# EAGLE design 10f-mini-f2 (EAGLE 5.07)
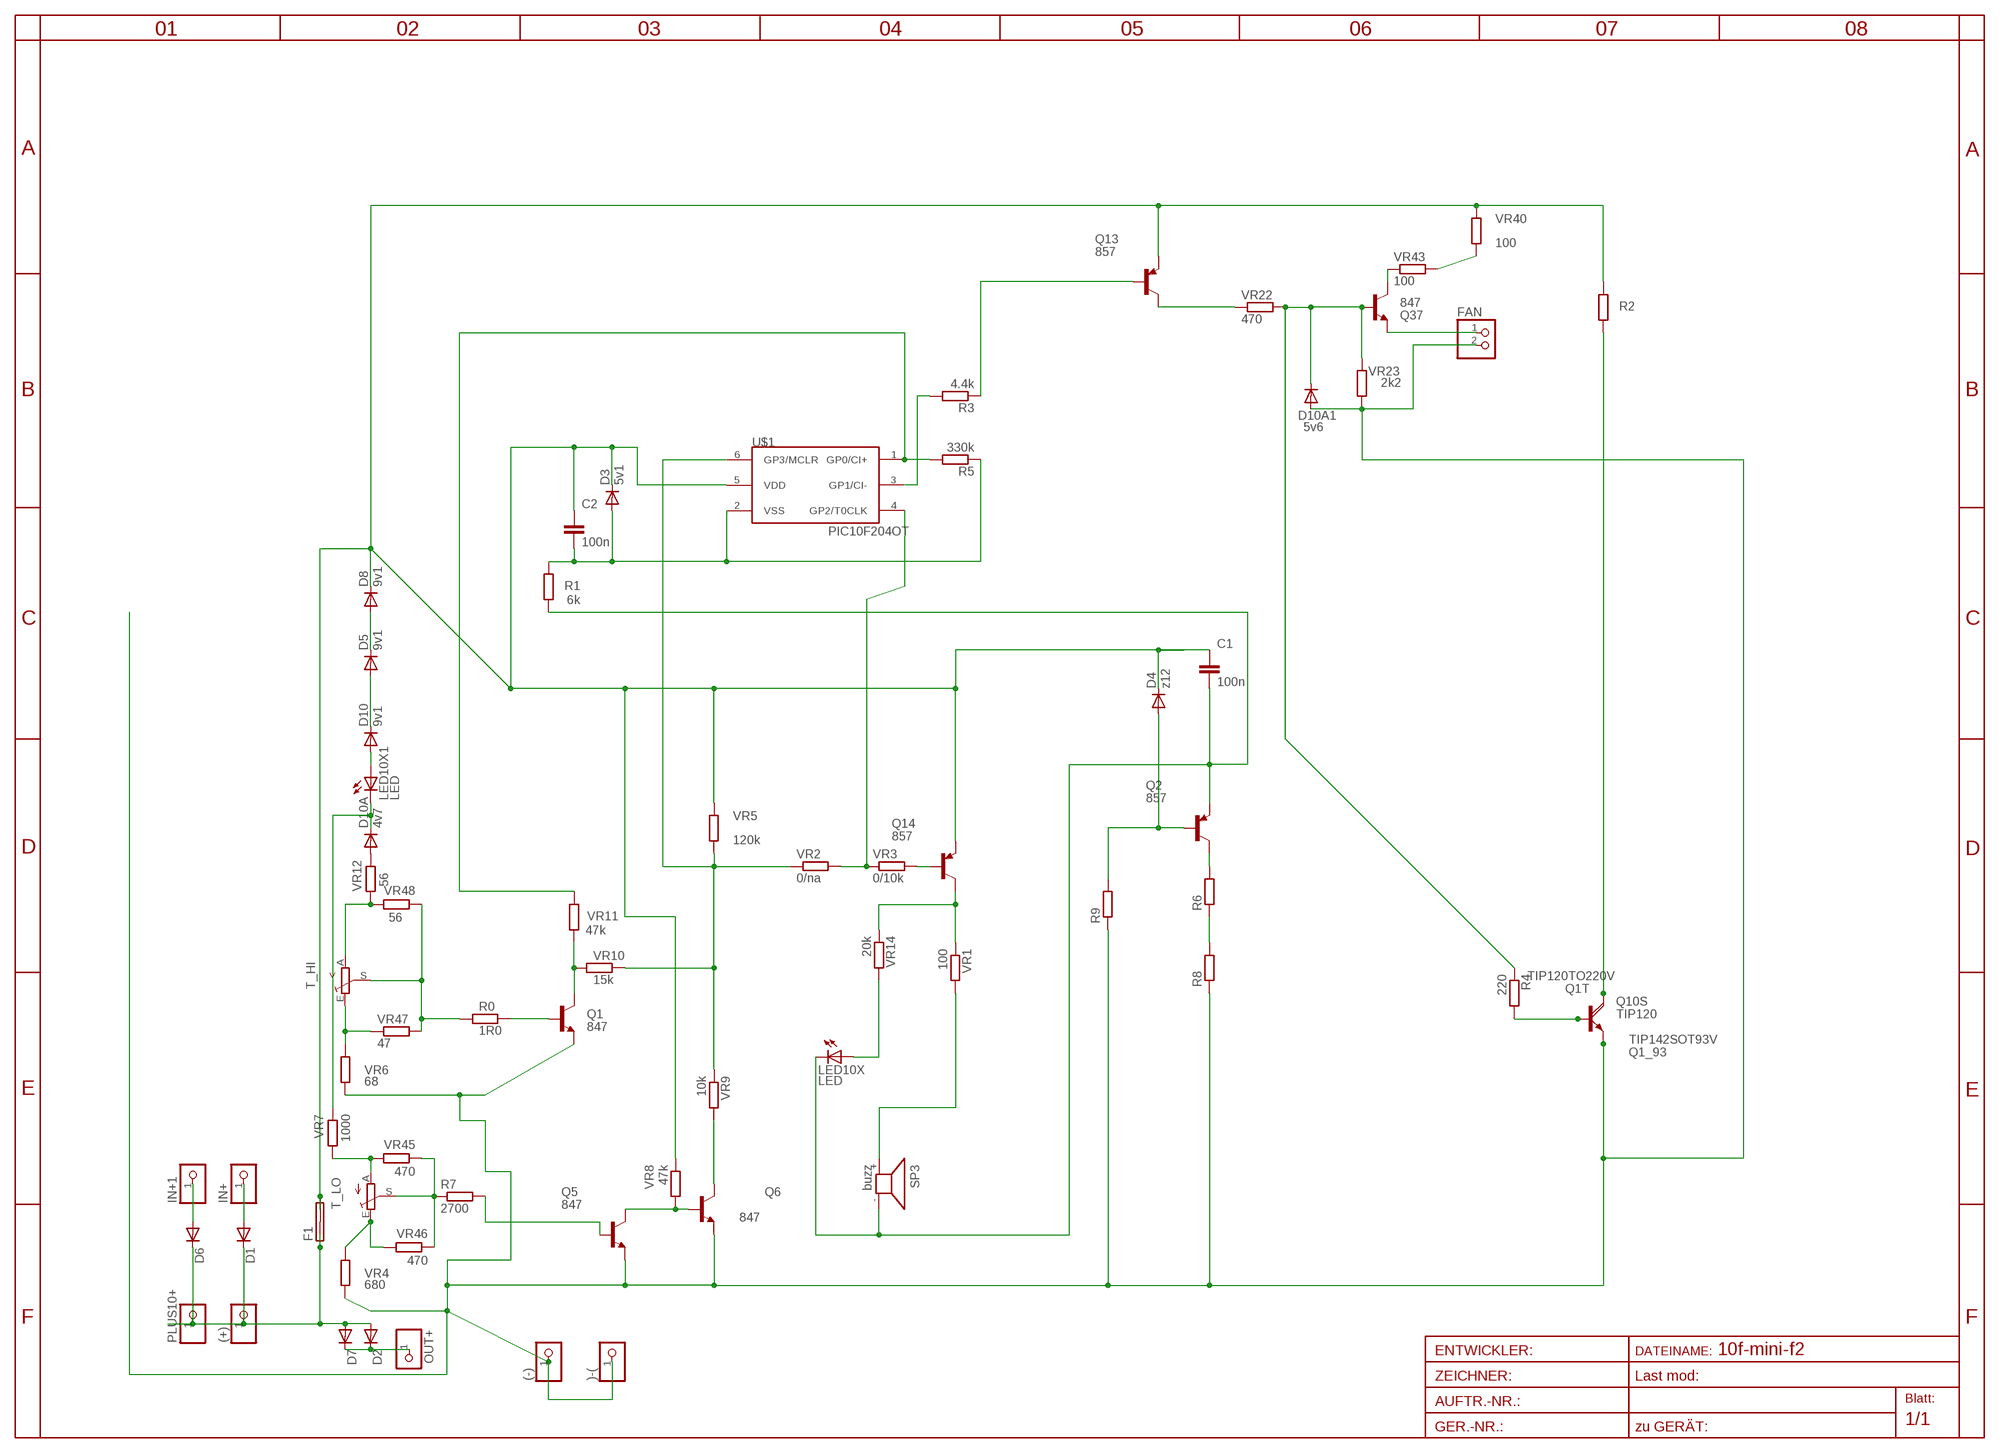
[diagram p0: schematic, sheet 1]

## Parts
(+)  PINHD-1X14.5MM  [1X4MM5]
(-)  PINHD-1X14.5MM  [1X4MM5]
)-(  PINHD-1X11X0.4  [1X01]
C1  100n  C-EUC1206  [C1206]
C2  100n  C-EUC1206  [C1206]
D1  DIODE-SMC  [SMC]
D2  DIODE-SMC  [SMC]
D3  5v1  DIODE-MINIMELF  [MINIMELF]
D4  z12  DIODE-MINIMELF  [MINIMELF]
D5  9v1  DIODE-MINIMELF  [MINIMELF]
D6  DIODE-SMC  [SMC]
D7  DIODE-SMC  [SMC]
D8  9v1  DIODE-MINIMELF  [MINIMELF]
D10  9v1  DIODE-MINIMELF  [MINIMELF]
D10A  4v7  DIODE-MINIMELF  [MINIMELF]
D10A1  5v6  DIODE-MINIMELF  [MINIMELF]
F1  SHK20L7MM5  [7MM5]
FAN  PINHD-1X2STR  [1X02]
IN+  PINHD-1X12MM3  [1X2MM3]
IN+1  PINHD-1X12MM3  [1X2MM3]
LED10X  LED  LEDCHIPLED_1206  [CHIPLED_1206]
LED10X1  LED  LEDCHIPLED_1206  [CHIPLED_1206]
OUT+  PINHD-1X12MM3  [1X2MM3]
PLUS10+  PINHD-1X11X0.4  [1X01]
Q1  847  BC847CSMD  [SOT23]
Q1_93  TIP142SOT93V  [SOT93V]
Q1T  TIP120TO220V  [TO220AV]
Q2  857  BC857CSMD  [SOT23-BEC]
Q5  847  BC847CSMD  [SOT23]
Q6  847  BC847CSMD  [SOT23]
Q10S  TIP120  TIP120DPAK  [D-PAK_TO252AA]
Q13  857  BC857CSMD  [SOT23-BEC]
Q14  857  BC857CSMD  [SOT23-BEC]
Q37  847  BC847CSMD  [SOT23]
R0  1R0  R-EU_R1206  [R1206]
R1  6k  R-EU_R1206  [R1206]
R2  R-EU_CERAM40  [CERAM40]
R3  4.4k  R-EU_R0805  [R0805]
R4  220  R-EU_R0805  [R0805]
R5  330k  R-EU_R0805  [R0805]
R6  R-EU_R1206  [R1206]
R7  2700  R-EU_R0805  [R0805]
R8  R-EU_R1206  [R1206]
R9  R-EU_R1206  [R1206]
SP3  buzz  KSS12017MM  [KSS1202]
T_HI  TRIM_EU-S64W  [S64W]
T_LO  TRIM_EU-S64W  [S64W]
U$1  PIC10F204OT  [SOT23-6]
VR1  100  R-EU_R0805  [R0805]
VR2  0/na  R-EU_R0805  [R0805]
VR3  0/10k  R-EU_R1206  [R1206]
VR4  680  R-EU_R0805  [R0805]
VR5  120k  R-EU_R0805  [R0805]
VR6  68  R-EU_R0805  [R0805]
VR7  1000  R-EU_R0805  [R0805]
VR8  47k  R-EU_R0805  [R0805]
VR9  10k  R-EU_R0805  [R0805]
VR10  15k  R-EU_R1206  [R1206]
VR11  47k  R-EU_R0805  [R0805]
VR12  56  R-EU_R0805  [R0805]
VR14  20k  R-EU_R0805  [R0805]
VR22  470  R-EU_R0805  [R0805]
VR23  2k2  R-EU_R0805  [R0805]
VR40  100  R-EU_R1206  [R1206]
VR43  100  R-EU_R1206  [R1206]
VR45  470  R-EU_R0805  [R0805]
VR46  470  R-EU_R0805  [R0805]
VR47  47  R-EU_R0805  [R0805]
VR48  56  R-EU_R0805  [R0805]

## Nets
B: R0.1 T_HI.S VR47.2 VR48.1
BUZZ+: SP3.+ VR1.2
FPLUS: C1.1 C2.1 D3.C D4.C D8.C F1.2A F1.2B Q13.E Q14.E R2.2 U$1.5(VDD) VR5.1 VR8.1 VR40.1
GP3: U$1.4(GP2/T0CLK) VR2.2 VR3.1
IN+: D1.A IN+.1
INPLUS: (+).1 D1.C D2.A D6.C D7.A F1.1A F1.1B PLUS10+.1
LEDA: LED10X.A VR14.2
N$1: D6.A IN+1.1
N$2: Q1.3(C) VR10.1 VR11.1
N$3: Q5.3(C) Q6.1(B) VR8.2
N$4: D10.A LED10X1.A
N$5: Q6.3(C) VR9.2
N$6: U$1.6(GP3/MCLR) VR2.1 VR5.2 VR9.1 VR10.2
N$7: Q1.1(B) R0.2
N$8: Q14.C VR1.1 VR14.1
N$9: D4.A Q2.B R9.2
N$10: Q14.B VR3.2
N$11: R5.2 U$1.1(GP0/CI+) VR11.2
N$12: R6.1 R8.2
N$13: Q2.C R6.2
N$14: T_HI.A VR12.2 VR48.2
N$15: D5.A D10.C
N$16: D5.C D8.A
N$17: D10A.C LED10X1.C VR7.1
N$18: D10A.A VR12.1
N$19: T_LO.A VR7.2 VR45.2
N$22: R7.1 T_LO.S VR45.1 VR46.1
N$23: Q13.B R3.1
N$24: T_LO.E VR4.1 VR46.2
N$25: Q1_93.B Q1T.B Q10S.1(B) R4.2
N$128: T_HI.E VR6.1 VR47.1
N$136: FAN.1 Q37.2(E)
N$159: Q13.C VR22.1
N$163: VR40.2 VR43.2
N$164: Q37.3(C) VR43.1
N$168: Q5.1(B) R7.2
N$179: D10A1.C Q37.1(B) R4.1 VR22.2 VR23.1
OUT+: D2.C D7.C OUT+.1
Q10C: Q1_93.C Q1T.C Q10S.4(C) R2.1
V12: C1.2 LED10X.C Q2.E R1.1 SP3.-
VDF: R3.2 U$1.3(GP1/CI-)
VSS1: C2.2 D3.A R1.2 R5.1 U$1.2(VSS)
VSS2: (-).1 )-(.1 D10A1.A FAN.2 Q1.2(E) Q1_93.E Q1T.E Q5.2(E) Q6.2(E) Q10S.3(E) R8.1 R9.1 VR4.2 VR6.2 VR23.2

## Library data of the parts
(+) (-) )-( IN+ IN+1 OUT+ PLUS10+ = pinhead:PINHD-1X1: PIN HEADER
C1 C2 = rcl:C-EU: CAPACITOR, European symbol
D1-D8 D10 D10A D10A1 = diode:DIODE-: DIODE
F1 = fuse:SHK20L: FUSE HOLDER 5 x 20 mm, SH contact, SHH1 Schukat, E1073 Buerklin
FAN = pinhead:PINHD-1X2: PIN HEADER
LED10X LED10X1 = led:LED: LED
Q1 Q5 Q6 Q37 = transistor-npn:BC847*: NPN Transistor
Q1_93 = transistor-power:TIP142: NPN DARLINGTON TRANSISTOR
Q1T Q10S = transistor-power:TIP120: NPN DARLINGTON TRANSISTOR
Q2 Q13 Q14 = transistor-pnp:BC857*: PNP Transistror
R0 R1 R3-R5 VR1-VR12 VR14 VR22 VR23 VR40 VR43 VR45-VR48 = rcl-2:R-EU_: RESISTOR, European symbol
R2 R6-R9 = rcl:R-EU_: RESISTOR, European symbol
SP3 = buzzer:KSS1201: SPEAKER
T_HI T_LO = pot:TRIM_EU-: POTENTIOMETER
U$1 = microchip-3:PIC10F2*: uPC nW 0,25/0,5k Program Flash memory Comparator

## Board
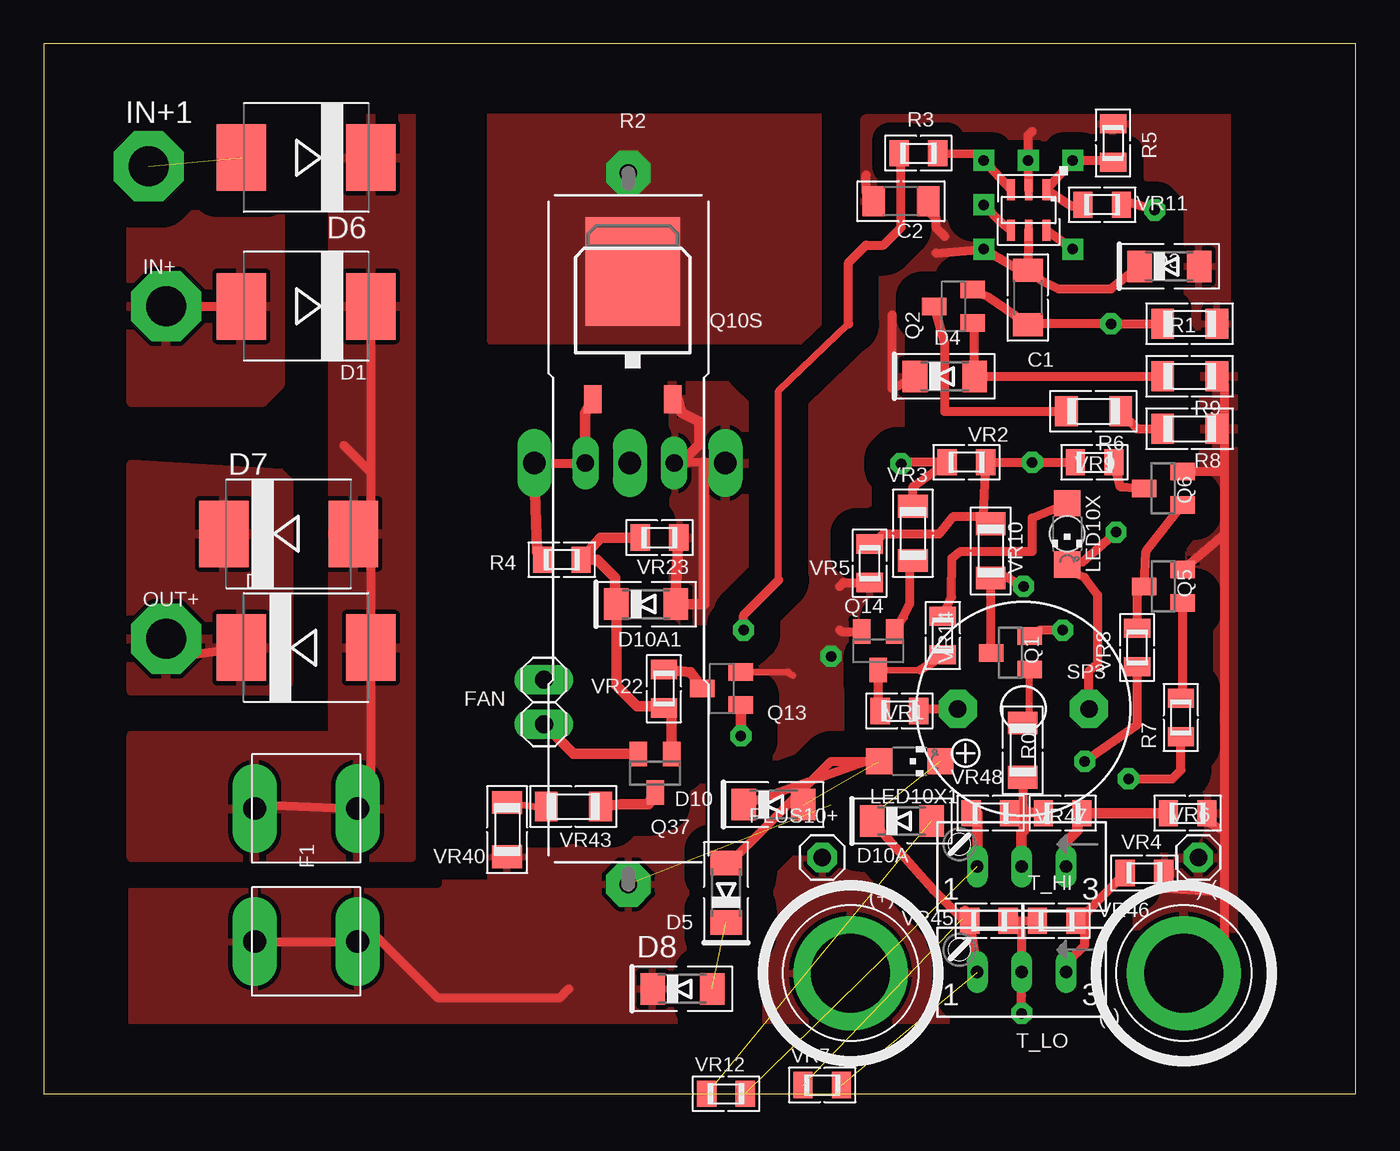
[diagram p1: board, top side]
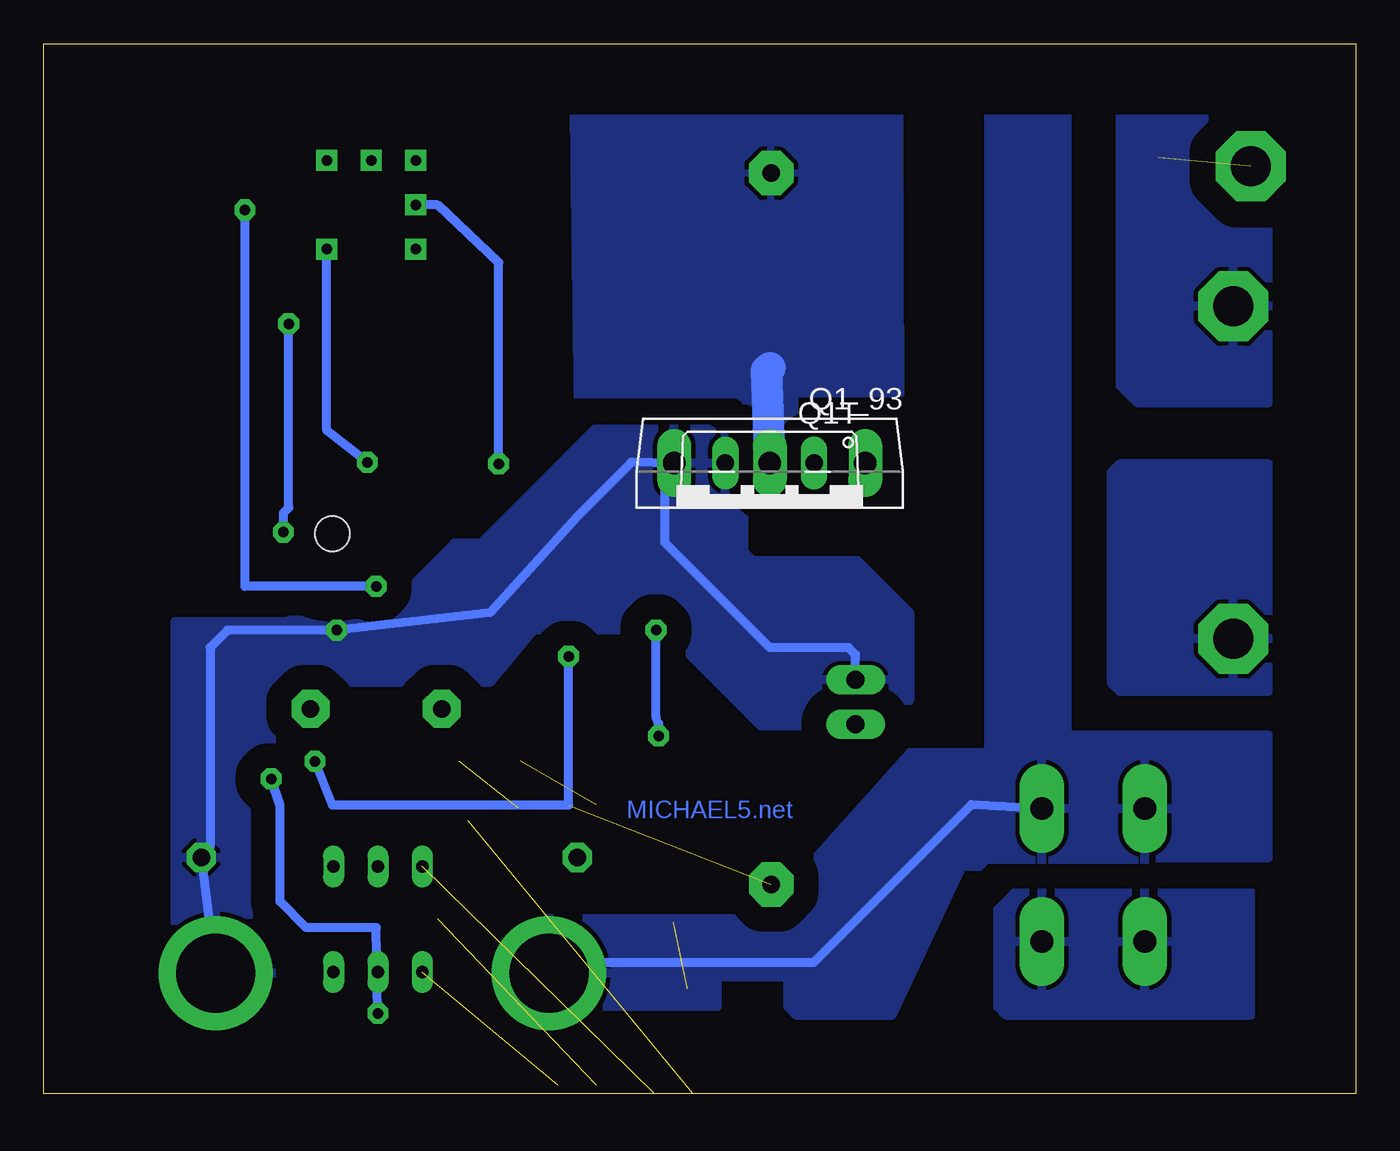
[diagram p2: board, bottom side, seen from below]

Size 75 x 60 mm. Coordinates in mm from the lower left corner, seen from the top.
Outline: 0,0 75,0 75,60 0,60 0,0
Copper layers (1*16): Top 0.035mm / dielectric 1.5mm / Bottom 0.035mm
Design rules "default *": minimum track width 8mil, minimum drill 4mil, track to track 8mil, track to pad 8mil, pad to pad 8mil, via to via 8mil, smd to smd 8mil, copper to edge 4mm, drill to drill 8mil, minimum pad ring 10mil, minimum via ring 8mil, stop-mask expansion 4mil, vias tented up to drill 0mil, thermal gap 10mil
Holes 2 mm at 58.5,32

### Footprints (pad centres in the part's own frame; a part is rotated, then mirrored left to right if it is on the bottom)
1X4MM5 = drill 4.5 pad 6.35 round: 1 0,0
1X01 = drill 1 pad 1.676 octagon: 1 0,0
C1206 = smd 1.3 x 1.7: 1 -1.55,0; 2 1.55,0
SMC = smd 2.8 x 3.8: A 3.7,0; C -3.7,0
MINIMELF = smd 1.4 x 1.8: A 1.7,0; C -1.7,0
7MM5 = drill 1.3 pad 2.54 long: 1A -3.8,2.94; 1B -3.8,-2.94; 2A 3.8,2.94; 2B 3.8,-2.94
1X02 = drill 1.016 pad 1.676 long: 1 -1.27,0; 2 1.27,0
1X2MM3 = drill 2.3 pad 4 octagon: 1 0,0
CHIPLED_1206 = smd 1.5 x 1.5: A 0,-1.75; C 0,1.75
SOT23 = smd 1 x 1.4: 1 -0.95,-1.1; 2 0.95,-1.1; 3 0,1.1
SOT93V = drill 1.3 pad 1.676 long: B -5.461,-2.54; C 0,-2.54; E 5.461,-2.54
TO220AV = drill 1 pad 1.27 long: B -2.54,-2.54; C 0,-2.54; E 2.54,-2.54
SOT23-BEC = smd 1 x 1.4: B -0.95,-1.1; C 0,1.1; E 0.95,-1.1
D-PAK_TO252AA = smd 1 x 1.6: 1 -2.28,-4.8; 3 2.28,-4.8 | smd 5.4 x 6.2: 4 0,2.5
R1206 = smd 1.3 x 1.7: 1 -1.55,0; 2 1.55,0
CERAM40 = drill 1 pad 2.54 octagon: 1 -20.32,0; 2 20.32,0
R0805 = smd 1.1 x 1.5: 1 -1.1,0; 2 1.1,0
KSS1202 = drill 1 pad 2.159 octagon: + 3.75,0; - -3.75,0
S64W = drill 0.7 long: A 2.54,1.27; E -2.54,1.27; S 0,1.27
SOT23-6 = smd 0.45 x 1.2: 1 -1.016,-1.15; 2 0,-1.15; 3 1.016,-1.15; 4 1.016,1.15; 5 0,1.15; 6 -1.016,1.15

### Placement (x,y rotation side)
(+)  46.12,6.89 0 top
(-)  65.17,6.89 0 top
)-(  66,13.5 0 top
C1  56.25,45.5 270 top
C2  49,51 180 top
D1  15,45 180 top
D2  15,25.5 0 top
D3  64.33,47.28 0 top
D4  51.5,41 0 top
D5  39,11.5 90 top
D6  15,53.5 180 top
D7  14,32 0 top
D8  36.5,6 0 top
D10  41.72,16.52 0 top
D10A  49.05,15.6 0 top
D10A1  34.44,27.97 0 top
F1  15,12.5 270 top
FAN  28.59,22.38 90 top
IN+  7,45 0 top
IN+1  6,53 0 top
LED10X  58.5,32 180 top
LED10X1  49.5,19 270 top
OUT+  7,26 0 top
PLUS10+  44.5,13.5 0 top
Q1  55.26,25.19 90 top
Q1_93  33.5,33.5 180 bottom
Q1T  33.5,33.5 180 bottom
Q2  52,45 90 top
Q5  64,29 90 top
Q6  63.99,34.6 90 top
Q10S  33.67,44.48 0 top
Q13  38.75,23.16 90 top
Q14  47.71,25.3 180 top
Q37  34.94,18.32 180 top
R0  55.96,19.63 90 top
R1  65.5,44 0 top
R2  33.42,32.29 270 top
R3  50,53.75 0 top
R4  29.61,30.51 180 top
R5  61.12,54.33 270 top
R6  60,39 180 top
R7  65,21.5 90 top
R8  65.5,38 180 top
R9  65.5,41 180 top
SP3  56,22 180 top
T_HI  55.9,14.26 180 top
T_LO  55.9,8.22 180 top
U$1  56.3,50.5 180 top
VR1  48.91,21.88 0 top
VR2  52.75,36.08 180 top
VR3  49.69,32.03 270 top
VR4  62.92,12.62 0 top
VR5  47.22,30.31 90 top
VR6  65.38,16.03 0 top
VR7  44.5,0.5 0 top
VR8  62.5,25.5 90 top
VR9  60.07,36.08 0 top
VR10  54.13,31.02 90 top
VR11  60.5,50.8 180 top
VR12  39,0 0 top
VR14  51.39,26.19 90 top
VR22  35.45,23.15 270 top
VR23  35.2,31.78 0 top
VR40  26.49,15.09 90 top
VR43  30.27,16.41 180 top
VR45  54.03,9.88 180 top
VR46  57.89,9.88 0 top
VR47  58.25,16.03 180 top
VR48  54.12,16.03 180 top

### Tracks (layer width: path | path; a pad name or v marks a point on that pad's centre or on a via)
B
  Top 0.406: 55.9,14.89 56.03,15.02
  Top 0.5: 56.02,16.08 R0.1
  Top 0.61: 56.28,16.1 56.02,16.08 VR48.1 | 56.28,16.1 VR47.2 | T_HI.S 55.9,14.89 | 56.03,15.02 56.03,15.84 56.28,16.1
BUZZ+
  Top 0.5: SP3.+ 50.14,22 VR1.2
FPLUS  (via drill 0.6 pad 1.2)  (1 unrouted)
  Top 0.406: Q13.E 42.56,24.1 42.5,24.1 42.82,23.91
  Top 0.5: 56.28,46.76 U$1.5 | 56.28,46.76 v53.74,48.26 51.01,48.03 | D3.C 61,46 58,46 57,46.5 56.45,47.05 C1.1 56.28,47.42 56.28,46.76 | VR8.1 62.5,21.1 v59.5,19 | 48.5,44.5 48.5,40.3 D4.C | F1.2B F1.2A 19.08,8.92 22.5,5.5 29.5,5.5 30,6 | C2.1 50.55,50.45 51,50 51,49.5 51.5,49 | Q14.E 45.59,26.41 45.5,26.5 | VR5.1 45.71,29.21 45.5,29
  Bottom 0.5: v59.5,19 58.5,16.5 45,16.5 v45,25
  pour Top (isolate 1.5, rank 2): 39.77,3.08 5.05,3.08 5.05,12.07 25.57,12.07 25.5,13.5 36.72,18.07 36.72,20.61 42,25.18 42.5,40 45.5,43 46.5,43 46.5,49.5 48.2,51.2 49.33,51.2 54.13,48.46 54.13,47.63 51.5,45 49.5,45 49,44.5 49,16.03 40.79,10.95 40.79,3.33
  pour Bottom (isolate 1.5, rank 3): 6,11.5 19.5,11.5 20.5,10.5 20.5,5 20,4.5 6,4.5
GP3  (via drill 0.6 pad 1.2)
  Top 0.5: U$1.4 54.76,49.78 v53.74,50.8 | VR3.1 49.69,34.69 51.5,36 51.71,36 VR2.2 49.08,36.08 v49,36
  Bottom 0.5: v49,36 49,47.5 52.5,50.8 v53.74,50.8
IN+
  Top 0.5: 6.3,45 IN+.1 D1.A
  pour Top (isolate 1.5, rank 2): 5,56 13.5,56 13.5,40.5 12.5,39.5 5,39.5
  pour Bottom (isolate 1.5, rank 2): 5,56 13.5,56 13.5,40.5 12.5,39.5 5,39.5
INPLUS
  Top 0.5: 18.7,35.5 18.7,25.7 18,25 D2.A 18.7,17.08 F1.1A 12.52,16.52 12,16 12,16.26 F1.1B | 18.7,35.5 D1.C | 18.7,35.5 17.17,37.03
  Bottom 0.5: F1.1A 21.98,16.52 31,7.5 45.51,7.5 (+).1
  pour Top (isolate 2): 55,15 55,3.08 41.29,3.08 41.29,13.21 41.33,15
  pour Bottom (isolate 1.422, rank 4): 10.5,19.5 25.5,19.5 34,10 47,10 48.5,9 48.5,5 36.5,5 36.5,6.7 32.5,6.7 32.5,5 32,4.5 26.5,4.5 22.5,13 10.5,13
  pour Top (isolate 1.5): 21,56 21,13.5 5,13.5 5,20.5 16.5,20.5 16.5,56
  pour Bottom (isolate 1.5): 21,56 21,13.5 5,13.5 5,20.5 16.5,20.5 16.5,56
LEDA
  Top 0.5: VR14.2 51.89,28.39 51.9,30.6 52.4,31 56.5,31 56.5,32.9 LED10X.A
N$1  (1 unrouted)
N$2  (via drill 0.6 pad 1.2)
  Top 0.5: VR11.1 62.09,50.91 v63.5,50.5 | v56,29 54.9,29.6 VR10.1 54.16,29.57 Q1.3
  Bottom 0.5: v56,29 63.5,29 v63.5,50.5
N$3
  Top 0.5: VR8.2 62.5,28.5 Q5.3 63,31 Q6.1
N$4  (1 unrouted)
N$5
  Top 0.5: VR9.2 61.52,34.69 Q6.3
N$6  (via drill 0.6 pad 1.2)
  Top 0.5: v58.82,48.26 U$1.6 | VR5.2 47.22,31.29 48,32 51.19,32 52,33 53.7,33 | VR9.1 v56.5,36.08 VR2.1 53.7,33 | 53.7,33 VR10.2
  Bottom 0.5: v58.82,48.26 58.82,37.9 v56.5,36.08
N$7
  Top 0.406: Q1.1 56.36,21.66 R0.2
N$8
  Top 0.406: 50.9,24.72 51.58,24.8 VR14.1 | Q14.C 50.11,24.22
  Top 0.5: 50.11,24.22 50.9,24.72 | Q14.C 47.71,21.98 VR1.1
N$9
  Top 0.5: R9.2 D4.A 53.2,43.95 Q2.B
N$10
  Top 0.5: Q14.B 49.16,27.26 49.5,28 49.5,29.91 VR3.2
N$11  (via drill 0.6 pad 1.2)
  Top 0.5: VR11.2 58.75,50.72 U$1.1 v58.82,53.34 61.08,53.34 R5.2
N$12
  Top 0.5: R6.1 61.55,38.95 62.5,38 R8.2
N$13
  Top 0.5: R6.2 51.5,39 51.5,42.9 Q2.C
N$14  (1 unrouted)
  Top 0.406: 53.36,16.04 VR48.2
  Top 0.61: T_HI.A 53.36,16.04
N$15
  Top 0.5: D5.A 39.5,13.5 45,19 47,19 D10.C
N$16  (1 unrouted)
N$17  (2 unrouted)
  Top 0.406: D10A.C 47.85,16.32
  Top 0.5: D10A.C 50.85,11.65 52.5,10 52.67,10.5
N$18  (1 unrouted)
N$19  (1 unrouted)
  Top 0.5: VR45.2 53.28,7.73 T_LO.A
N$22  (via drill 0.6 pad 1.2)
  Top 0.5: v55.9,4.6 55.9,5.6 T_LO.S 55.9,7.55 55.9,9.3 55.08,9.92 VR45.1 VR46.1 | v62,18 64.5,18 65,18.5 R7.1
  Bottom 0.5: v55.9,4.6 56,9.5 60,9.5 61.5,11 61.5,16.5 v62,18
N$23  (via drill 0.6 pad 1.2)
  Top 0.406: 42,29.35 42,40.18 46,44
  Top 0.5: 46,44 46,47.5 47,48.5 48,48.5 49,49.5 49,53.75 R3.1 49,53.7 | v40,26.5 40,27.35 42,29.35
  Top 0.61: Q13.B v39.85,20.44
  Bottom 0.5: v39.85,20.44 39.85,21.15 40,21.5 v40,26.5
N$24
  Top 0.5: T_LO.E 58.65,7.65 59.5,8.5 59.5,9.83 VR46.2 59.44,9.94 59.5,10 59.5,10.25 VR4.1
N$25
  Top 0.5: Q1_93.B Q1T.B
  Top 0.61: Q1_93.B 28.21,30.96 R4.2 | Q1T.B 30.93,38.88 Q10S.1
N$128
  Top 0.406: 59.07,16.03 VR47.1 59.07,16.03
  Top 0.61: T_HI.E 58.44,14.38 59.07,15.02 59.07,16.03 | 59.07,16.03 VR6.1
N$136
  Top 0.61: Q37.2 30.29,19.42 FAN.1
N$159
  Top 0.61: VR22.1 36.96,24.1 Q13.C
N$163
  Top 0.406: VR40.2 28.44,16.38 VR43.2
N$164
  Top 0.61: VR43.1 33.01,16.54 34.56,16.54 Q37.3
N$168
  Top 0.5: Q5.1 65.1,22.7 R7.2
N$179
  Top 0.61: Q37.1 35.89,21.75 VR22.2 35.39,22.13 33.93,22.13 32.74,23.32 D10A1.C 32.66,28.05 32.66,29.5 31.64,30.51 R4.1 31.83,31.78 VR23.1
OUT+
  Top 0.5: OUT+.1 7.8,25 D2.C
  pour Top (isolate 1.5, rank 3): 5,36 13.5,35.5 14,35 14,23.5 13.5,23 5,23
  pour Bottom (isolate 1.5, rank 3): 5,36 13.5,36 14,35.5 14,23.5 13.5,23 5,23
Q10C
  Top 1.8: Q10S.4 33.5,46.98
  Bottom 1.8: Q1_93.C 33.67,41.33 33.5,41.5
  pour Top (isolate 0.813, no thermals): 25.55,60.2 44.27,60.2 44.27,43 25.55,43
  pour Bottom (isolate 1.5, rank 3): 26.05,55.88 44.73,55.88 44.48,37.1 32.05,37.1 32.05,39.95 32,40 26,40
V12  (via drill 0.6 pad 1.2)
  Top 0.5: Q2.E 54.05,45.5 55.5,44.5 55.9,44.1 C1.2 56.3,44 v61,44 R1.1 | SP3.- 59.75,24.15 60.25,24.6 60.25,28.5 59.5,29.5 58.5,29.88 LED10X.C 59.39,30.39 v61.3,32.1
  Bottom 0.5: v61.3,32.1 61.3,33.2 61,33.5 v61,44
VDF  (via drill 0.6 pad 1.2)
  Top 0.5: U$1.3 v53.74,53.34 53.38,53.7 R3.2
VSS1  (via drill 0.6 pad 1.2)
  Top 0.5: U$1.2 v56.28,53.34 56.28,54.78 56.5,55 | 47.5,50.5 47.53,50.53 C2.2 47.5,51 47,51.5 47,52.5
  pour Top (isolate 1): 46.9,50.62 46.9,55.74 47.41,55.99 67.67,55.99 67.67,43.81 66.15,43.59 65.37,44.59 65.37,50.93 61.63,53.2 61.63,53.7 61.12,54.21 57.57,54.21 57.05,54.7 55.02,54.7 54.52,53.45 53.76,54.21 48.93,54.21 48.42,53.7 48.42,50.36
VSS2  (via drill 0.6 pad 1.2)
  Top 0.5: VR6.2 66.47,15.53 67.5,15 | 67.5,11.5 67.5,8.72 (-).1 | 67.5,11.5 67.5,15 | R9.1 67,41 67.5,40.5 67.5,38 | 67.5,15 67.5,32 | 67.5,32 67.5,35.5 | 67.5,35.5 67.5,38 | VR4.2 64.18,11.72 67.5,11.5 | Q1.2 56.96,26.5 v58.25,26.5 | Q5.2 67.27,31.77 67.5,32 | Q6.2 67.45,35.55 67.5,35.5 | Q1_93.E 37.74,36.1 Q1T.E | 67.5,38 R8.1
  Top 0.61: 37.74,36.1 37.74,27.97 D10A1.A 36.14,29.07 36.21,30.26 VR23.2 | Q1T.E 36.47,36.1 37.48,37.12 37.48,38.4 36.47,38.92 36.23,39.66 Q10S.3
  Bottom 0.5: Q1_93.E 41.4,36.1 44.5,33 49.5,27.5 v58.25,26.5 64.5,26.5 65.5,25.5 65.5,14.08 )-(.1 (-).1 | Q1_93.E 38.5,36.1 | FAN.2 28.59,25.09 29,25.5 33.5,25.5 39.5,31.5 39.5,35.73 Q1_93.E
  pour Bottom (isolate 1.422, rank 2): 62,8.5 62,4.5 67.5,4.5 67.5,27 61,27 60.5,27.5 55.5,27.5 51.5,31.5 50,31.5 43.5,38 37,38 35,37 35,31 34.5,30.5 28.5,30.5 25.5,27.5 25.5,22.5 27,21 34,21 39.5,26.5 47,26.5 49.5,23.5 60,23.5 60.5,18 60.5,10
  pour Top (isolate 1.5, rank 3): 35.5,40.5 39,40.5 40.5,39 40.5,29 38.5,27 36.5,27 36,27.5 36,39
  pour Top (isolate 1.5, rank 3): 66.5,41.5 68,41.5 68,4.5 67.5,4 63,4 62.5,4.5 62.5,12 63.5,13 63.5,13.5 65.5,15.5 65.5,40

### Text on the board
Bottom: MICHAEL5.net
tTest: 4v4
Document: 1m | 10u | 10u | 300u | 2mA | 500u | 1m | 2m | 300u | 300u | 30u | 5m | 14m | 12m | 500u | 5m | 5m | 5m | 5m | 5m | 5m | 40m | 40m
